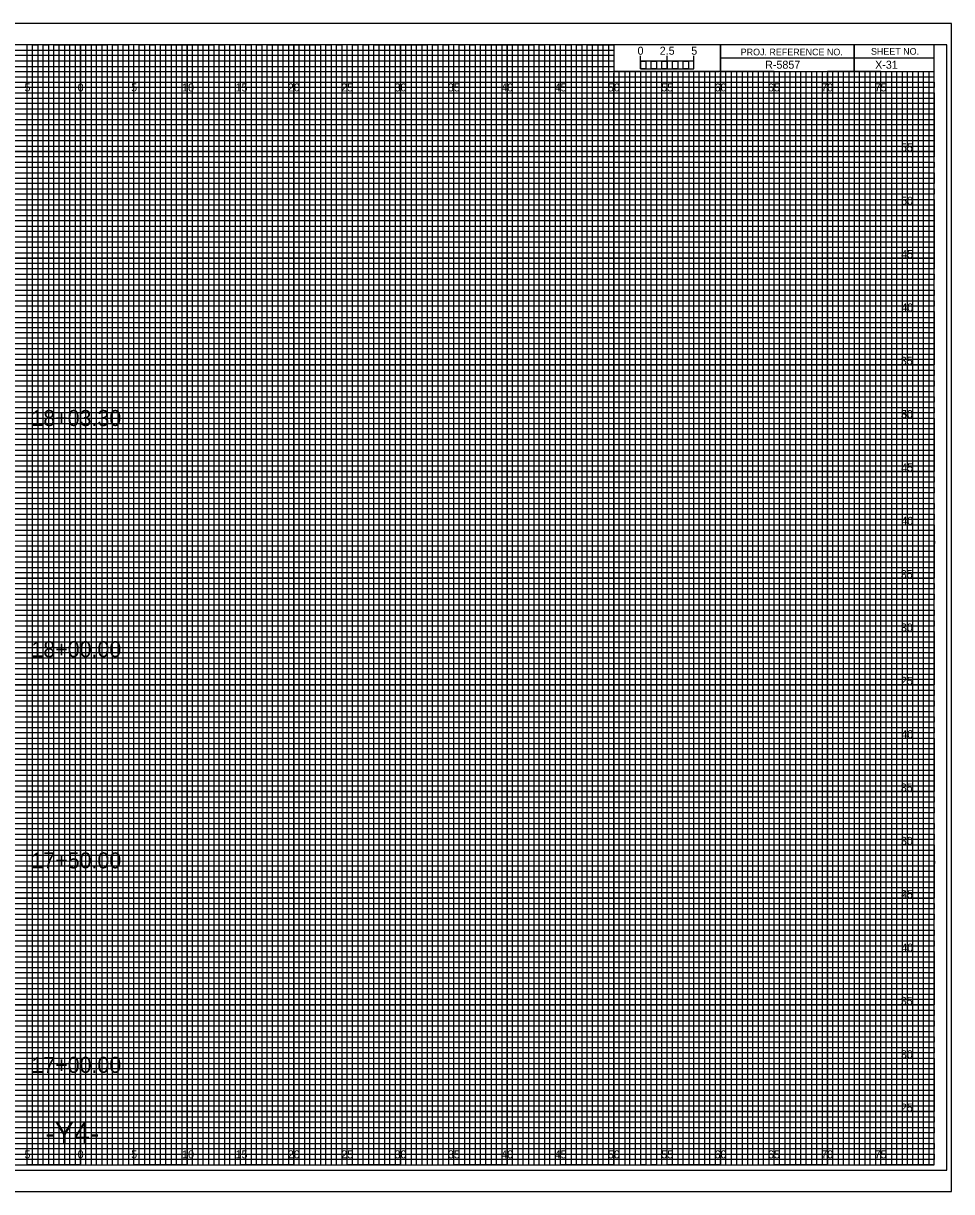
# Model space of a CAD drawing. Extents: x -7 to 162, y 107 to 217.
# Drawn here: x 74.6 to 161.7, y 107.5 to 217 of the extents above; entities that cross this region are included whole.
import ezdxf

# ---------------------------------------------------------------- set-up
doc = ezdxf.new("R2010")
doc.units = 0
for name, color, linetype in [('Exist XS Center Line Elevation Label', 7, 'Continuous'), ('Exist XS Ground Line', 7, 'Continuous'), ('Prop CMT Pvmt Course 1', 7, 'Continuous'), ('Prop CMT Pvmt Course 1 Wedge', 7, 'Continuous'), ('Prop CMT Pvmt Course 2', 7, 'Continuous'), ('Prop CMT Pvmt Course 2 Wedge', 7, 'Continuous'), ('Prop CMT Pvmt Course 3', 7, 'Continuous'), ('Prop CMT Pvmt Surface', 7, 'Continuous'), ('Prop CMT Pvmt Wedge Surface 1', 7, 'Continuous'), ('Prop CMT Shld Paved Course 1', 7, 'Continuous'), ('Prop CMT Shld Paved Course 2', 7, 'Continuous'), ('Prop CMT Shld Paved Course 3', 7, 'Continuous'), ('Prop CMT Slope Grass', 7, 'Continuous'), ('Prop CMT Subgrade Earthwork', 7, 'Continuous'), ('Raster_Level_0', 7, 'Continuous'), ('Scratch_Level_0', 7, 'Continuous')]:
    doc.layers.add(name, color=color, linetype=linetype)

msp = doc.modelspace()

# ---------------------------------------------------------------- linework, layer by layer
at = {"layer": 'Exist XS Center Line Elevation Label'}
for points in [[(72.5, 110), (77.5, 110), (77.5, 215), (82.5, 215), (82.5, 110), (87.5, 110), (87.5, 215), (92.5, 215), (92.5, 110), (97.5, 110), (97.5, 215), (102.5, 215), (102.5, 110), (107.5, 110), (107.5, 215), (112.5, 215), (112.5, 110), (117.5, 110), (117.5, 215), (122.5, 215), (122.5, 110), (127.5, 110), (127.5, 215), (129.97, 215), (130, 215), (130, 212.5), (132.5, 212.5), (132.5, 110), (137.5, 110), (137.5, 212.5), (142.5, 212.5), (142.5, 110), (147.5, 110), (147.5, 212.5), (152.5, 212.5), (152.5, 110), (157.5, 110), (157.5, 212.5)], [(0, 212.5), (137.5, 212.5)], [(0, 202.5), (160, 202.5), (160, 207.5), (0, 207.5)], [(0, 192.5), (160, 192.5), (160, 197.5), (0, 197.5)], [(0, 182.5), (160, 182.5), (160, 187.5), (0, 187.5)], [(0, 172.5), (160, 172.5), (160, 177.5), (0, 177.5)], [(0, 162.5), (160, 162.5), (160, 167.5), (0, 167.5)], [(0, 152.5), (160, 152.5), (160, 157.5), (0, 157.5)], [(0, 142.5), (160, 142.5), (160, 147.5), (0, 147.5)], [(0, 132.5), (160, 132.5), (160, 137.5), (0, 137.5)], [(0, 122.5), (160, 122.5), (160, 127.5), (0, 127.5)], [(0, 112.5), (160, 112.5), (160, 117.5), (0, 117.5)]]:
    msp.add_lwpolyline(points, dxfattribs=at)
at = {"layer": 'Exist XS Ground Line'}
for p, q in [((75, 215), (70, 215)), ((75, 110), (75, 215)), ((85, 215), (80, 215)), ((80, 215), (80, 110)), ((85, 110), (85, 215)), ((95, 215), (90, 215)), ((90, 215), (90, 110)), ((95, 110), (95, 215)), ((105, 215), (100, 215)), ((100, 215), (100, 110)), ((105, 110), (105, 215)), ((115, 215), (110, 215)), ((110, 215), (110, 110)), ((115, 110), (115, 215)), ((125, 215), (120, 215)), ((120, 215), (120, 110)), ((125, 110), (125, 215)), ((130, 215), (130, 110)), ((135, 110), (135, 212.5)), ((145, 212.5), (140, 212.5)), ((140, 212.5), (140, 110)), ((145, 110), (145, 212.5)), ((155, 212.5), (150, 212.5)), ((150, 212.5), (150, 110)), ((155, 110), (155, 212.5)), ((80, 110), (75, 110)), ((90, 110), (85, 110)), ((100, 110), (95, 110)), ((110, 110), (105, 110)), ((120, 110), (115, 110)), ((130, 110), (125, 110)), ((140, 110), (135, 110)), ((150, 110), (145, 110)), ((160, 110), (155, 110)), ((160, 110), (160, 110))]:
    msp.add_line(p, q, dxfattribs=at)
for points in [[(0, 210), (160, 210), (160, 205), (0, 205)], [(0, 200), (160, 200), (160, 195), (0, 195)], [(0, 190), (160, 190), (160, 185), (0, 185)], [(0, 180), (160, 180), (160, 175), (0, 175)], [(0, 170), (160, 170), (160, 165), (0, 165)], [(0, 160), (160, 160), (160, 155), (0, 155)], [(0, 150), (160, 150), (160, 145), (0, 145)], [(0, 140), (160, 140), (160, 135), (0, 135)], [(0, 130), (160, 130), (160, 125), (0, 125)], [(0, 120), (160, 120), (160, 115), (0, 115)]]:
    msp.add_lwpolyline(points, dxfattribs=at)
at = {"layer": 'Prop CMT Pvmt Course 1'}
msp.add_lwpolyline([(-5.4, 109.5), (161.2, 109.5), (161.2, 215), (-5.4, 215)], close=True, dxfattribs=at)
at = {"layer": 'Prop CMT Pvmt Course 2'}
for p, q in [((75, 110), (75, 215)), ((80, 110), (80, 215)), ((85, 110), (85, 215)), ((90, 110), (90, 215)), ((95, 110), (95, 215)), ((100, 110), (100, 215)), ((105, 110), (105, 215)), ((110, 110), (110, 215)), ((115, 110), (115, 215)), ((120, 110), (120, 215)), ((125, 110), (125, 215)), ((130, 110), (130, 212.34)), ((135, 110), (135, 212.34)), ((140, 110), (140, 212.34)), ((145, 110), (145, 212.34)), ((150, 110), (150, 212.34)), ((155, 110), (155, 212.34)), ((0, 210), (160, 210)), ((0, 205), (160, 205)), ((0, 200), (160, 200)), ((0, 195), (160, 195)), ((0, 190), (160, 190)), ((0, 185), (160, 185)), ((0, 180), (160, 180)), ((0, 175), (160, 175)), ((0, 170), (160, 170)), ((0, 165), (160, 165)), ((0, 160), (160, 160)), ((0, 155), (160, 155)), ((0, 150), (160, 150)), ((0, 145), (160, 145)), ((0, 140), (160, 140)), ((0, 135), (160, 135)), ((0, 130), (160, 130)), ((0, 125), (160, 125)), ((0, 120), (160, 120)), ((0, 115), (160, 115))]:
    msp.add_line(p, q, dxfattribs=at)
at = {"layer": 'Prop CMT Pvmt Course 3'}
for p, q in [((161.65, 217), (-6.7, 217)), ((-6.7, 107.5), (161.65, 107.5))]:
    msp.add_line(p, q, dxfattribs=at)
at = {"layer": 'Prop CMT Shld Paved Course 1'}
for p, q in [((133.5, 212.5), (133, 212.5)), ((133, 212.5), (133, 110)), ((133.5, 110), (133.5, 212.5)), ((134.5, 212.5), (134, 212.5)), ((134, 212.5), (134, 110)), ((134.5, 110), (134.5, 212.5)), ((133, 110), (132.5, 110)), ((134, 110), (133.5, 110))]:
    msp.add_line(p, q, dxfattribs=at)
for points in [[(75, 110), (75.5, 110), (75.5, 215), (76, 215), (76, 110)], [(76, 110), (76.5, 110), (76.5, 215), (77, 215), (77, 110)], [(77.5, 110), (78, 110), (78, 215), (78.5, 215), (78.5, 110)], [(78.5, 110), (79, 110), (79, 215), (79.5, 215), (79.5, 110)], [(80, 110), (80.5, 110), (80.5, 215), (81, 215), (81, 110)], [(81, 110), (81.5, 110), (81.5, 215), (82, 215), (82, 110)], [(82.5, 110), (83, 110), (83, 215), (83.5, 215), (83.5, 110)], [(83.5, 110), (84, 110), (84, 215), (84.5, 215), (84.5, 110)], [(85, 110), (85.5, 110), (85.5, 215), (86, 215), (86, 110)], [(86, 110), (86.5, 110), (86.5, 215), (87, 215), (87, 110)], [(87.5, 110), (88, 110), (88, 215), (88.5, 215), (88.5, 110)], [(88.5, 110), (89, 110), (89, 215), (89.5, 215), (89.5, 110)], [(90, 110), (90.5, 110), (90.5, 215), (91, 215), (91, 110)], [(91, 110), (91.5, 110), (91.5, 215), (92, 215), (92, 110)], [(92.5, 110), (93, 110), (93, 215), (93.5, 215), (93.5, 110)], [(93.5, 110), (94, 110), (94, 215), (94.5, 215), (94.5, 110)], [(95, 110), (95.5, 110), (95.5, 215), (96, 215), (96, 110)], [(96, 110), (96.5, 110), (96.5, 215), (97, 215), (97, 110)], [(97.5, 110), (98, 110), (98, 215), (98.5, 215), (98.5, 110)], [(98.5, 110), (99, 110), (99, 215), (99.5, 215), (99.5, 110)], [(100, 110), (100.5, 110), (100.5, 215), (101, 215), (101, 110)], [(101, 110), (101.5, 110), (101.5, 215), (102, 215), (102, 110)], [(102.5, 110), (103, 110), (103, 215), (103.5, 215), (103.5, 110)], [(103.5, 110), (104, 110), (104, 215), (104.5, 215), (104.5, 110)], [(105, 110), (105.5, 110), (105.5, 215), (106, 215), (106, 110)], [(106, 110), (106.5, 110), (106.5, 215), (107, 215), (107, 110)], [(107.5, 110), (108, 110), (108, 215), (108.5, 215), (108.5, 110)], [(108.5, 110), (109, 110), (109, 215), (109.5, 215), (109.5, 110)], [(110, 110), (110.5, 110), (110.5, 215), (111, 215), (111, 110)], [(111, 110), (111.5, 110), (111.5, 215), (112, 215), (112, 110)], [(112.5, 110), (113, 110), (113, 215), (113.5, 215), (113.5, 110)], [(113.5, 110), (114, 110), (114, 215), (114.5, 215), (114.5, 110)], [(115, 110), (115.5, 110), (115.5, 215), (116, 215), (116, 110)], [(116, 110), (116.5, 110), (116.5, 215), (117, 215), (117, 110)], [(117.5, 110), (118, 110), (118, 215), (118.5, 215), (118.5, 110)], [(118.5, 110), (119, 110), (119, 215), (119.5, 215), (119.5, 110)], [(120, 110), (120.5, 110), (120.5, 215), (121, 215), (121, 110)], [(121, 110), (121.5, 110), (121.5, 215), (122, 215), (122, 110)], [(122.5, 110), (123, 110), (123, 215), (123.5, 215), (123.5, 110)], [(123.5, 110), (124, 110), (124, 215), (124.5, 215), (124.5, 110)], [(125, 110), (125.5, 110), (125.5, 215), (126, 215), (126, 110)], [(126, 110), (126.5, 110), (126.5, 215), (127, 215), (127, 110)], [(127.5, 110), (128, 110), (128, 215), (128.5, 215), (128.5, 110)], [(128.5, 110), (129, 110), (129, 215), (129.5, 215), (129.5, 110)], [(130, 110), (130.5, 110), (130.5, 212.5), (131.01, 212.5), (131.01, 110)], [(131, 110), (131.5, 110), (131.5, 212.5), (132, 212.5), (132, 110)], [(135, 110), (135.49, 110), (135.49, 212.5), (136, 212.5), (136, 110)], [(136, 110), (136.5, 110), (136.5, 212.5), (137.03, 212.5), (137.03, 110)], [(137.5, 110), (138, 110), (138, 212.5), (138.5, 212.5), (138.5, 110)], [(138.5, 110), (139, 110), (139, 212.5), (139.5, 212.5), (139.5, 110)], [(140, 110), (140.5, 110), (140.5, 212.5), (141, 212.5), (141, 110)], [(141, 110), (141.5, 110), (141.5, 212.5), (142, 212.5), (142, 110)], [(142.5, 110), (143, 110), (143, 212.5), (143.5, 212.5), (143.5, 110)], [(143.5, 110), (144, 110), (144, 212.5), (144.5, 212.5), (144.5, 110)], [(145, 110), (145.5, 110), (145.5, 212.5), (146, 212.5), (146, 110)], [(146, 110), (146.5, 110), (146.5, 212.5), (147, 212.5), (147, 110)], [(147.5, 110), (148, 110), (148, 212.5), (148.5, 212.5), (148.5, 110)], [(148.5, 110), (149, 110), (149, 212.5), (149.5, 212.5), (149.5, 110)], [(150, 110), (150.5, 110), (150.5, 212.5), (151, 212.5), (151, 110)], [(151, 110), (151.5, 110), (151.5, 212.5), (152, 212.5), (152, 110)], [(152.5, 110), (153, 110), (153, 212.5), (153.5, 212.5), (153.5, 110)], [(153.5, 110), (154, 110), (154, 212.5), (154.5, 212.5), (154.5, 110)], [(155, 110), (155.5, 110), (155.5, 212.5), (156, 212.5), (156, 110)], [(156, 110), (156.5, 110), (156.5, 212.5), (157, 212.5), (157, 110)], [(157.5, 110), (158, 110), (158, 212.5), (158.5, 212.5), (158.5, 110)], [(158.5, 110), (159, 110), (159, 212.5), (159.5, 212.5), (159.5, 110)]]:
    msp.add_lwpolyline(points, dxfattribs=at)
at = {"layer": 'Prop CMT Shld Paved Course 2'}
for p, q in [((132.5, 212.75), (132.5, 213.95)), ((132.5, 213.45), (132.5, 213.95)), ((135, 212.75), (135, 213.95)), ((137.5, 212.75), (137.5, 213.95)), ((137.5, 213.45), (137.5, 213.95))]:
    msp.add_line(p, q, dxfattribs=at)
for points in [[(137.5, 213.45), (132.5, 213.45), (132.5, 212.75), (137.5, 212.75)], [(132.5, 213.45), (133, 213.45), (133, 212.75), (132.5, 212.75)], [(133.5, 213.45), (134, 213.45), (134, 212.75), (133.5, 212.75)], [(134.5, 213.45), (135, 213.45), (135, 212.75), (134.5, 212.75)], [(135.5, 213.45), (136, 213.45), (136, 212.75), (135.5, 212.75)], [(136.5, 213.45), (137, 213.45), (137, 212.75), (136.5, 212.75)]]:
    msp.add_lwpolyline(points, close=True, dxfattribs=at)
at = {"layer": 'Prop CMT Shld Paved Course 3'}
msp.add_lwpolyline([(-6.7, 107.5), (161.65, 107.5), (161.65, 217), (-6.7, 217)], close=True, dxfattribs=at)
at = {"layer": 'Prop CMT Slope Grass'}
for p, q in [((152.5, 215), (152.5, 212.5)), ((152.5, 212.5), (152.5, 215)), ((160, 213.75), (140, 213.75)), ((140, 213.75), (140, 212.5)), ((140, 212.5), (160, 212.5))]:
    msp.add_line(p, q, dxfattribs=at)
for points in [[(160, 215), (0, 215), (0, 110), (160, 110)], [(140, 215), (130, 215), (130, 212.52), (140, 212.52)], [(160, 215), (140, 215), (140, 212.5), (160, 212.5)]]:
    msp.add_lwpolyline(points, close=True, dxfattribs=at)
at = {"layer": 'Scratch_Level_0'}
for p, q in [((0, 214.5), (130, 214.5)), ((130, 213.99), (0, 213.99)), ((130, 214.5), (130, 213.99)), ((0, 213.5), (130, 213.5)), ((130, 212.94), (0, 212.94)), ((130, 213.5), (130, 212.94)), ((0, 212), (160, 212))]:
    msp.add_line(p, q, dxfattribs=at)
for points in [[(0, 211.5), (135, 211.5), (160, 211.5), (160, 211), (0, 211)], [(0, 210.5), (160, 210.5), (160, 209.5), (0, 209.5)], [(0, 209), (160, 209), (160, 208.5), (0, 208.49)], [(0, 208), (160, 208), (160, 207), (0, 207)], [(0, 206.5), (160, 206.5), (160, 206), (0, 206)], [(0, 205.5), (160, 205.5), (160, 204.5), (0, 204.5)], [(0, 204), (160, 204), (160, 203.5), (0, 203.5)], [(0, 203), (160, 203), (160, 202), (0, 202)], [(0, 201.5), (160, 201.5), (160, 201), (0, 201)], [(0, 200.5), (160, 200.5), (160, 199.5), (0, 199.5)], [(0, 199), (160, 199), (160, 198.5), (0, 198.5)], [(0, 198), (160, 198), (160, 196.97), (160, 196.5), (160, 196), (0, 196)], [(0, 197), (160, 197), (160, 196.5), (0, 196.5)], [(0, 195.5), (160, 195.5), (160, 194.5), (0, 194.52)], [(0, 194.52), (160, 194.5), (160, 194), (0, 194)], [(0, 193.5), (160, 193.5), (160, 193), (0, 193)], [(0, 192), (160, 192), (160, 191.5), (0, 191.5)], [(0, 191), (160, 191), (160, 190.5), (0, 190.5)], [(-0.04, 189.44), (160, 189.44), (160, 188.94), (-0.04, 188.94)], [(0, 188.5), (160, 188.5), (160, 188), (0, 188)], [(0, 187), (160, 187), (160, 186.5), (0, 186.5)], [(0, 186), (160, 186), (160, 185.5), (0, 185.5)], [(0, 184.5), (160, 184.5), (160, 184), (0, 184)], [(0, 183.5), (160, 183.5), (160, 183), (0, 183)], [(0, 182), (160, 182), (160, 181.5), (0, 181.5)], [(0, 181), (160, 181), (160, 180.5), (0, 180.5)], [(0, 179.5), (160, 179.5), (160, 178.99), (0, 179)], [(0, 178.5), (160, 178.5), (160, 178), (0, 178)], [(0, 177), (160, 177), (160, 176.5), (0, 176.5)], [(0, 176), (160, 176), (160, 175.5), (0, 175.5)], [(0, 174.5), (160, 174.5), (160, 174), (0, 174)], [(0, 173.5), (160, 173.5), (160, 173), (0, 173)], [(0, 172), (160, 172), (160, 171.5), (0, 171.5)], [(0, 171), (160, 171), (160, 170.5), (0, 170.5)], [(0, 169.5), (160, 169.5), (160, 169), (0, 169)], [(0, 168.5), (160.03, 168.46), (160, 168), (0, 168)], [(0, 167), (160, 167), (160, 166.5), (0, 166.5)], [(0, 166), (160, 166), (160, 165.5), (0, 165.5)], [(0, 164.5), (160, 164.5), (160, 164), (0, 164)], [(0, 163.5), (160, 163.5), (160, 163), (0, 163)], [(0, 162), (160, 162), (160, 161.5), (0, 161.5)], [(0, 161), (160, 161), (160, 160.5), (0, 160.5)], [(0, 159.5), (160, 159.5), (160, 159), (0, 159)], [(0, 158.5), (160, 158.5), (160, 158), (0, 158)], [(0, 157), (160, 157), (160, 156.5), (0, 156.5)], [(0, 156), (160, 156), (160, 155.5), (0, 155.5)], [(0, 154.5), (160, 154.5), (160, 154), (0, 154)], [(0, 153.5), (160, 153.5), (160, 153), (0, 153)], [(0, 152), (160, 152), (160, 151.5), (0, 151.5)], [(0, 151), (160, 151), (160, 150.5), (0, 150.5)], [(0, 149.5), (160, 149.5), (160, 148.99), (0, 149)], [(0, 148.5), (160, 148.5), (160, 148), (0, 148)], [(0, 147), (160, 147), (160, 146.5), (0, 146.5)], [(0, 146), (160, 146), (160, 145.5), (0, 145.5)], [(0, 144.5), (160, 144.5), (160, 144), (0, 144)], [(0, 143.5), (160, 143.5), (160, 143), (0, 143)], [(0, 142), (160, 142), (160, 141.5), (0, 141.5)], [(0, 141), (160, 141), (160, 140.5), (0, 140.5)], [(0, 139.5), (160, 139.5), (160, 139), (0, 139)], [(0, 138.5), (160.03, 138.46), (160, 138), (0, 138)], [(0, 137), (160, 137), (160, 136.5), (0, 136.5)], [(0, 136), (160, 136), (160, 135.5), (0, 135.5)], [(0, 134.5), (160, 134.5), (160, 134), (0, 134)], [(0, 133.5), (160, 133.5), (160, 133), (0, 133)], [(0, 132), (160, 132), (160, 131.5), (0, 131.5)], [(0, 131), (160, 131), (160, 130.5), (0, 130.5)], [(0, 129.5), (160, 129.5), (160, 129), (0, 129)], [(0, 128.5), (160, 128.5), (160, 128), (0, 128)], [(0, 127), (160, 127), (160, 126.5), (0, 126.5)], [(0, 126), (160, 126), (160, 125.5), (0, 125.5)], [(0, 124.5), (160, 124.5), (160, 124), (0, 124)], [(0, 123.5), (160, 123.5), (160, 123), (0, 123)], [(0, 122), (160, 122), (160, 121.5), (0, 121.5)], [(0, 121), (160, 121), (160, 120.5), (0, 120.5)], [(0, 119.5), (160, 119.5), (160, 119), (0, 119)], [(0, 118.5), (160, 118.5), (160, 118), (0, 118)], [(0, 117), (160, 117), (160, 116.5), (0, 116.5)], [(0, 116), (160, 116), (160, 115.5), (0, 115.5)], [(0, 114.5), (160, 114.5), (160, 114), (0, 114)], [(0, 113.5), (160, 113.5), (160, 113), (0, 113)], [(0, 112), (160, 112), (160, 111.5), (0, 111.5)], [(0, 111), (160, 111), (160, 110.5), (0, 110.5)]]:
    msp.add_lwpolyline(points, dxfattribs=at)

# ---------------------------------------------------------------- texts
at = {"layer": 'Prop CMT Pvmt Course 1 Wedge'}
msp.add_text('R-5857', height=0.75, dxfattribs=at).set_placement((144.17, 212.75))
at = {"layer": 'Prop CMT Pvmt Course 2 Wedge'}
msp.add_text('-Y4-', height=2, dxfattribs=at).set_placement((76.7, 112))
at = {"layer": 'Prop CMT Pvmt Course 3'}
for s, p in [('55', (156.9, 205)), ('50', (156.91, 200)), ('45', (156.92, 195)), ('40', (156.93, 190)), ('35', (156.88, 185)), ('30', (156.89, 180)), ('50', (156.91, 180)), ('45', (156.92, 175)), ('40', (156.93, 170)), ('35', (156.88, 165)), ('30', (156.89, 160)), ('25', (156.89, 155)), ('40', (156.93, 150)), ('35', (156.88, 145)), ('30', (156.89, 140)), ('25', (156.89, 135)), ('45', (156.92, 135)), ('40', (156.93, 130)), ('35', (156.88, 125)), ('30', (156.89, 120)), ('25', (156.89, 115))]:
    msp.add_text(s, height=0.75, dxfattribs=at).set_placement(p)
at = {"layer": 'Prop CMT Pvmt Surface'}
msp.add_text('X-31', height=0.75, dxfattribs=at).set_placement((154.48, 212.75))
at = {"layer": 'Prop CMT Pvmt Wedge Surface 1'}
for s, p in [('2.5', (134.29, 214.06)), ('5', (137.24, 214.06))]:
    msp.add_text(s, height=0.75, dxfattribs=at).set_placement(p)
at = {"layer": 'Prop CMT Shld Paved Course 2'}
msp.add_text('0', height=0.75, dxfattribs=at).set_placement((132.21, 214.06))
at = {"layer": 'Prop CMT Slope Grass'}
for s, p in [('PROJ. REFERENCE NO.', (141.88, 214)), ('SHEET NO.', (154.09, 214.06))]:
    msp.add_text(s, height=0.625, dxfattribs=at).set_placement(p)
at = {"layer": 'Prop CMT Subgrade Earthwork'}
for s, p in [('18+03.30', (75.39, 179.26)), ('18+00.00', (75.39, 157.59)), ('17+50.00', (75.39, 137.8)), ('17+00.00', (75.39, 118.63))]:
    msp.add_text(s, height=1.5, dxfattribs=at).set_placement(p)
at = {"layer": 'Raster_Level_0'}
for s, p in [('5', (74.74, 210.62)), ('0', (79.73, 210.62)), ('0', (79.73, 210.62)), ('5', (84.74, 210.62)), ('10', (89.52, 210.62)), ('15', (94.53, 210.62)), ('20', (99.43, 210.62)), ('25', (104.44, 210.62)), ('30', (109.43, 210.62)), ('35', (114.44, 210.62)), ('40', (119.43, 210.62)), ('45', (124.44, 210.62)), ('50', (129.43, 210.62)), ('55', (134.44, 210.62)), ('60', (139.43, 210.62)), ('65', (144.44, 210.62)), ('70', (149.43, 210.62)), ('75', (154.44, 210.62)), ('5', (74.74, 110.62)), ('0', (79.73, 110.62)), ('0', (79.73, 110.62)), ('5', (84.74, 110.62)), ('10', (89.52, 110.62)), ('15', (94.53, 110.62)), ('20', (99.43, 110.62)), ('25', (104.44, 110.62)), ('30', (109.43, 110.62)), ('35', (114.44, 110.62)), ('40', (119.43, 110.62)), ('45', (124.44, 110.62)), ('50', (129.43, 110.62)), ('55', (134.44, 110.62)), ('60', (139.43, 110.62)), ('65', (144.44, 110.62)), ('70', (149.43, 110.62)), ('75', (154.44, 110.62))]:
    msp.add_text(s, height=0.75, dxfattribs=at).set_placement(p)

doc.saveas('drawing.dxf')
